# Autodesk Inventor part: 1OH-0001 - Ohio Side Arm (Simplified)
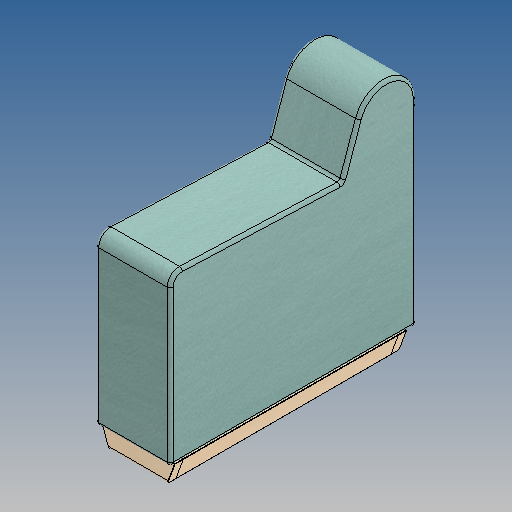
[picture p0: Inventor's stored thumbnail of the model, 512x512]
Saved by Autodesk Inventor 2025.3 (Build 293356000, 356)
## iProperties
Created: 2025-11
Part Number: 1OH-0001 - Ohio Side Arm (Simplified)
Material: Generic
Document SubType Name: Modeling
Designer: craig.ferris
Density: 1 g/cm^3
Appearance: CADET-ZEST SEAFOAM (219)
Author: craig.ferris
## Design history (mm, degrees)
derived "1OH-0001 - Ohio Side Arm with Upholstery (RevC).iam"
body "Solid1"
body "Solid2"
body "Solid3"
body "Solid4"
body "Solid5"
node "UPHOLSTERY 1OH-0001 (Rev C).ipt:1"
body "Solid6"
body "Solid7"
body "Solid8"
body "Solid9"
body "Solid10"
body "Solid11"
body "Solid12"
body "Solid13"
body "Solid14"
